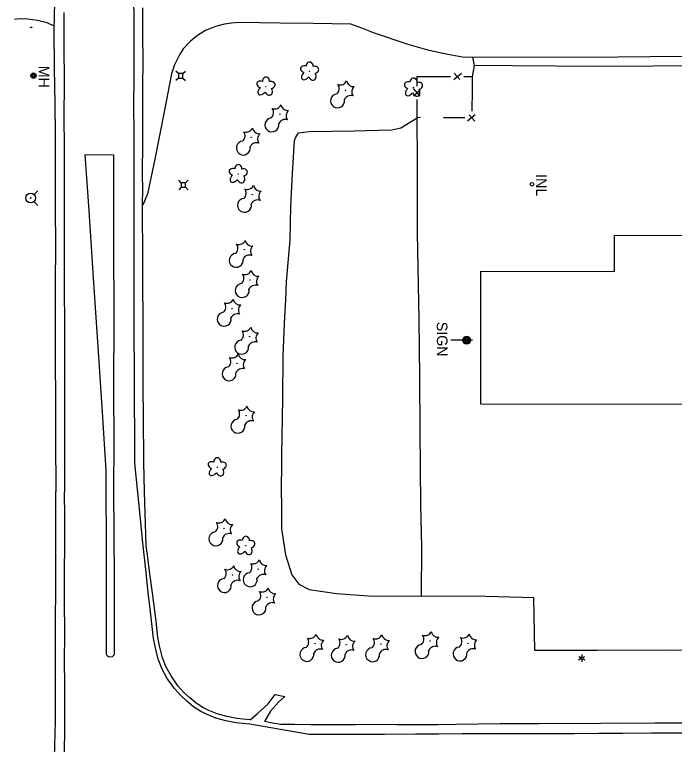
# Model space of a CAD drawing. Extents: x 588843 to 2552415, y 180129 to 269402.
# Drawn here: x 593172.9 to 593545.7, y 183989.9 to 184402 of the extents above; entities that cross this region are included whole.
import ezdxf

# ---------------------------------------------------------------- set-up
doc = ezdxf.new("R2010")
doc.units = 0
for name, color, linetype in [('Default', 7, 'Continuous'), ('E_AREA', 7, 'Continuous'), ('E_BLD', 7, 'Continuous'), ('E_DRN', 7, 'Continuous'), ('E_DRN_Text', 7, 'Continuous'), ('E_DWY', 7, 'Continuous'), ('E_FEN_P', 7, 'Continuous'), ('E_LAND_Vegetation', 7, 'Continuous'), ('E_LTG', 7, 'Continuous'), ('E_MISCPROP', 7, 'Continuous'), ('E_RDWY', 7, 'Continuous'), ('E_RDWY_C_and_G', 7, 'Continuous'), ('E_RDWY_Gravel', 7, 'Continuous'), ('E_SGN', 7, 'Continuous'), ('E_SGN_Text', 7, 'Continuous'), ('E_UTL_AG_Bold', 7, 'Continuous'), ('E_UTL_MH', 7, 'Continuous'), ('E_UTL_MH_Text', 7, 'Continuous'), ('E_UTL_WHydrant', 7, 'Continuous')]:
    doc.layers.add(name, color=color, linetype=linetype)

# ---------------------------------------------------------------- blocks, each defined once
blk = doc.blocks.new('CTRE')
at = {"layer": 'Default'}
blk.add_circle((0, 0), 0.223, dxfattribs=at)
for centre, start, end in [((-11.97, 8.96), 280.2067, 5.97162), ((1.81, 14.92), 220.21132, 305.97623), ((13.83, 5.89), 160.21133, 245.97624), ((-13.83, -5.9), 340.21132, 65.97623), ((-1.81, -14.93), 40.21133, 125.97624), ((12.03, -9.04), 185.92721, 100.25111)]:
    blk.add_arc(centre, 7.87, start, end, dxfattribs=at)
blk = doc.blocks.new('DTRE')
at = {"layer": 'Default'}
blk.add_circle((-0.18, 0), 0.183, dxfattribs=at)
for centre, major_axis, ratio in [((-1.87, 5.32), (1.36, -4.98), 0.782863), ((-5.87, 0.15), (4.93, -0.12), 0.832022), ((4.06, 2.74), (-5.27, -2.93), 0.691916), ((-2.49, -5.24), (1.8, 4.86), 0.716896), ((3.54, -3.71), (-5.01, 4.58), 0.560249)]:
    blk.add_ellipse(centre, major_axis=major_axis, ratio=ratio, start_param=1.570796, end_param=4.712389, dxfattribs=at)
blk = doc.blocks.new('LPOL')
at = {"layer": 'Default'}
for p, q in [((-4, 0), (-1.5, 0)), ((-0.75, 1.3), (-2, 3.46)), ((0.75, 1.3), (2, 3.46)), ((1.5, 0), (4, 0)), ((-2, -3.46), (-0.75, -1.3)), ((2, -3.46), (0.75, -1.3))]:
    blk.add_line(p, q, dxfattribs=at)
for radius in [1.5, 1.5, 1.5, 0.125]:
    blk.add_circle((0, 0), radius, dxfattribs=at)
blk = doc.blocks.new('MHO')
at = {"layer": 'Default'}
for centre, radius in [((0.08, -0.12), 3), ((0.08, -0.12), 2.43), ((0.07, -0.15), 1.94), ((0.02, -0.16), 1.21)]:
    blk.add_circle(centre, radius, dxfattribs=at)
blk = doc.blocks.new('MHT')
at = {"layer": 'E_UTL_MH_Text'}
blk.add_text('MH', height=12, dxfattribs=at).set_placement((-9.81, -6))
blk = doc.blocks.new('CULV2')
at = {"layer": 'E_DRN'}
blk.add_arc((20, 15), 24.6, 216.8699, 323.1301, dxfattribs=at)
blk = doc.blocks.new('HYD')
at = {"layer": 'Default'}
for p, q in [((-3.84, 3.84), (-8.32, 8.32)), ((3.84, 3.84), (8.32, 8.32))]:
    blk.add_line(p, q, dxfattribs=at)
for radius in [5.48, 0.42]:
    blk.add_circle((0, 0), radius, dxfattribs=at)
blk = doc.blocks.new('PED')
at = {"layer": 'Default'}
for p, q in [((-2.5, 2.5), (-5.33, 5.33)), ((2.5, 2.5), (5.33, 5.33)), ((-2.5, -2.5), (-5.33, -5.33)), ((2.5, -2.5), (5.33, -5.33))]:
    blk.add_line(p, q, dxfattribs=at)
blk.add_lwpolyline([(-2.5, -2.5), (2.5, -2.5), (2.5, 2.5), (-2.5, 2.5)], close=True, dxfattribs=at)
blk = doc.blocks.new('POLE')
at = {"layer": 'Default'}
for radius in [4.46, 3.35, 2.23, 1.12]:
    blk.add_circle((0, 0), radius, dxfattribs=at)
blk = doc.blocks.new('SIGN')
at = {"layer": 'Default'}
blk.add_text('SIGN', height=12, dxfattribs=at).set_placement((-18.55, -6))
blk = doc.blocks.new('INLT_18')
at = {"layer": 'E_DRN_Text'}
blk.add_text('INL', height=12, dxfattribs=at).set_placement((-11.03, -6))

msp = doc.modelspace()

# ---------------------------------------------------------------- linework, layer by layer
at = {"layer": 'E_AREA'}
msp.add_lwpolyline([(593431.59, 184377.93), (593432.5, 184373.17)], dxfattribs=at)
at = {"layer": 'E_BLD'}
msp.add_lwpolyline([(593436.4, 184257.03), (593511.82, 184256.91), (593511.85, 184277.37), (593631.64, 184277.17), (593631.66, 184286.82), (593660.64, 184286.78), (593660.63, 184281.05), (593685.36, 184281.01), (593685.2, 184182.16), (593667.98, 184182.19), (593667.94, 184156.61), (593567.5, 184156.78), (593567.54, 184181.81), (593436.27, 184182.03), (593436.4, 184257.03)], close=True, dxfattribs=at)
at = {"layer": 'E_DRN'}
msp.add_circle((593465.21, 184306.21), 1.04, dxfattribs=at)
at = {"layer": 'E_DWY'}
for points in [[(593631.69, 184413.71), (593631.67, 184373.35), (593604.85, 184372.88), (593564.43, 184373), (593502.95, 184372.78), (593454.12, 184373.01), (593432.5, 184373.17), (593431.48, 184366.85)], [(593195.22, 184395.42), (593191.39, 184397.27), (593185.78, 184398.7), (593180.14, 184399.39), (593176.04, 184399.69), (593172.93, 184399.27)], [(593550.18, 184378.37), (593513.66, 184377.95), (593470.82, 184377.84), (593426, 184377.94), (593417.66, 184379.46), (593407.11, 184381.69), (593395.36, 184385.08), (593375.64, 184391.63), (593369.17, 184394.36), (593362.89, 184396.66), (593341.55, 184397.01), (593323.04, 184397.1), (593299.63, 184397.51), (593295.54, 184397.19), (593291.52, 184396.66), (593286.51, 184395.29), (593280.75, 184392.96), (593276.21, 184390.1), (593272.35, 184386.92), (593268.25, 184382.72), (593266.13, 184379.26), (593263.3, 184373.56), (593261.65, 184368.64), (593257.65, 184348.09), (593252.09, 184320.4), (593248.08, 184300.88), (593245.28, 184294.32)], [(593323.63, 184129.02), (593323.87, 184153.18), (593324.38, 184185.29), (593324.62, 184209.34), (593325.48, 184227.67), (593326.23, 184240.93), (593326.6, 184251.11), (593328.55, 184274.9), (593329.02, 184293.67), (593330, 184312.2), (593331.12, 184330.87), (593331.74, 184332.8), (593333.23, 184335.24), (593339.34, 184335.91), (593364.65, 184336.4), (593386.05, 184337.01), (593391.08, 184338.04), (593400.42, 184343.69)], [(593402.45, 184125.26), (593401.98, 184167.17), (593401.81, 184197.24), (593401.41, 184229.76), (593400.56, 184278.64), (593400.59, 184318.89), (593400.42, 184343.72)], [(593323.63, 184129.02), (593323.68, 184111.58), (593325.91, 184096.93), (593329.53, 184085.67), (593333.48, 184080.36), (593339.36, 184077.44), (593354.79, 184075.02), (593372.94, 184073.72), (593402.81, 184073.66)], [(593582.78, 184042.97), (593543.17, 184043.07), (593501.9, 184042.83), (593466.83, 184042.85), (593466.18, 184072.61), (593439.11, 184073.34), (593402.81, 184073.66), (593402.96, 184101.6), (593402.45, 184125.26)]]:
    msp.add_lwpolyline(points, dxfattribs=at)
at = {"layer": 'E_FEN_P'}
for p, q in [((593421.09, 184365.32), (593425.34, 184369)), ((593421.29, 184369.01), (593424.48, 184365.39)), ((593402.07, 184355.96), (593398.35, 184360.18)), ((593398.37, 184356.13), (593401.97, 184359.34)), ((593433.03, 184345.44), (593428.79, 184341.74)), ((593432.84, 184341.74), (593429.65, 184345.36))]:
    msp.add_line(p, q, dxfattribs=at)
for points in [[(593400.33, 184361.61), (593400.31, 184367.06), (593407.04, 184367.05)], [(593407.04, 184367.05), (593419.22, 184367.03)], [(593426.76, 184367.01), (593431.51, 184367), (593431.43, 184359.57)], [(593431.43, 184359.57), (593431.29, 184347.39)], [(593402.24, 184343.85), (593400.42, 184343.72), (593400.37, 184354.07)], [(593427.37, 184343.73), (593415.19, 184343.74)]]:
    msp.add_lwpolyline(points, dxfattribs=at)
at = {"layer": 'E_RDWY'}
for points in [[(593242.46, 184132.19), (593240.85, 184148.67), (593240.82, 184164.6), (593240.73, 184183.98), (593240.65, 184202.42), (593240.54, 184220.47), (593240.49, 184297.36), (593240.52, 184313.89), (593240.45, 184335.12), (593240.29, 184350.9), (593240.44, 184366.42), (593240.41, 184382.33), (593240.4, 184397.38), (593240.34, 184413.18)], [(593200.74, 184403.27), (593200.67, 184385.8), (593200.9, 184362.53), (593200.78, 184344.77), (593200.97, 184326.46), (593200.99, 184307.37), (593200.99, 184282.12), (593201.02, 184252.6), (593201.09, 184221.67), (593201.07, 184185.18), (593201.11, 184151.98), (593201.12, 184132.26)], [(593224.67, 184134.06), (593224.65, 184144.7), (593222.6, 184177.41), (593220.19, 184214.41), (593217.46, 184253.38), (593215.06, 184291.14), (593212.74, 184323.09), (593228.77, 184322.88), (593228.76, 184273.93), (593228.98, 184230.54), (593228.88, 184191.32), (593228.98, 184159.57), (593228.84, 184134.04)], [(593228.84, 184134.04), (593229.19, 184083.4), (593229.22, 184041.59), (593229.11, 184040.53), (593227.97, 184039.4), (593226.76, 184039.23), (593226.02, 184039.44), (593225.21, 184039.94), (593224.93, 184040.58), (593224.79, 184041.58), (593224.81, 184103.77), (593224.67, 184134.06)], [(593197.27, 183805.54), (593197.44, 183822.71), (593197.76, 183835.89), (593198.18, 183850.92), (593198.49, 183867.63), (593198.81, 183882.18), (593199.13, 183891.59), (593199.38, 183906.39), (593199.77, 183920.52), (593200.02, 183936.64), (593200.27, 183958.27), (593200.61, 183972.92), (593201.11, 183986.41), (593201.34, 183997.65), (593201.39, 184009.18), (593201.22, 184023.93), (593201.2, 184036.88), (593201.27, 184052.35), (593201.19, 184071.31), (593201.18, 184086.47), (593201.23, 184103.49), (593201.26, 184118.09), (593201.12, 184132.26)], [(593251.42, 184049.75), (593249.8, 184063.22), (593248.43, 184075.61), (593247.02, 184088.74), (593245.41, 184103.65), (593244.29, 184115.13), (593243.3, 184124.84), (593242.46, 184132.19)], [(593306.1, 184003.8), (593310.18, 184007.26), (593316.1, 184012.72), (593320.22, 184018.08), (593325.5, 184017.03), (593322, 184013.76), (593317.53, 184008.59), (593314.03, 184002.86)], [(593559.88, 183996.27), (593544.92, 183996.23), (593532.75, 183996.23), (593516.32, 183996.12), (593502.75, 183996), (593488.8, 183995.9), (593476.34, 183995.88), (593464.33, 183995.88), (593452.39, 183995.9), (593439.7, 183995.86), (593425.74, 183995.79), (593412.44, 183995.74), (593399.36, 183995.72), (593381.98, 183995.54), (593366.43, 183995.53), (593351.75, 183995.49), (593339.4, 183995.44), (593305.91, 184001.31)]]:
    msp.add_lwpolyline(points, dxfattribs=at)
at = {"layer": 'E_RDWY_C_and_G'}
for points in [[(593305.91, 184001.31), (593301.87, 184001.61), (593297.98, 184002.11), (593292.18, 184003.3), (593286.59, 184004.78), (593281.65, 184006.8), (593278.05, 184008.57), (593273.99, 184011.2), (593270.28, 184014.26), (593266.78, 184017.5), (593263.27, 184021.45), (593259.19, 184027.2), (593256.22, 184032.44), (593254.09, 184038.11), (593252.34, 184045.1), (593251.42, 184049.75)], [(593306.1, 184003.8), (593302.13, 184004.1), (593298.39, 184004.58), (593292.75, 184005.74), (593287.39, 184007.16), (593282.68, 184009.08), (593279.28, 184010.75), (593275.48, 184013.22), (593271.93, 184016.14), (593268.56, 184019.25), (593265.23, 184023.01), (593261.31, 184028.54), (593258.49, 184033.51), (593256.48, 184038.85), (593254.78, 184045.64), (593253.87, 184050.24)]]:
    msp.add_lwpolyline(points, dxfattribs=at)
at = {"layer": 'E_RDWY_Gravel'}
for points in [[(593195.67, 184416.96), (593195.17, 184393.38), (593195.19, 184371.76), (593195.67, 184351.65), (593195.84, 184334.51), (593195.83, 184315.34), (593195.77, 184293.18), (593195.96, 184271.16), (593195.88, 184250.04), (593195.85, 184228.6), (593195.91, 184206.82), (593196, 184184), (593196.06, 184162.17), (593196.15, 184132.7)], [(593246.35, 184132.48), (593245.99, 184149.18), (593245.82, 184175.7), (593245.63, 184190.91), (593245.53, 184205.49), (593245.5, 184220.98), (593245.27, 184297.56), (593245.38, 184300.64), (593245.27, 184314.1), (593245.4, 184327.5), (593245.46, 184346.59), (593245.4, 184362.19), (593245.49, 184375.02), (593245.41, 184390.88), (593245.34, 184405.88)], [(593195.42, 183982.48), (593195.95, 184002.85), (593195.97, 184014.46), (593196.03, 184027.87), (593196.08, 184040.2), (593196.05, 184051.67), (593196.07, 184062.97), (593196.28, 184074.49), (593196.25, 184091.41), (593196.19, 184108.64), (593196.28, 184121.87), (593196.15, 184132.7)], [(593253.87, 184050.24), (593252.91, 184059.48), (593250.89, 184075.43), (593249.33, 184086.19), (593247.96, 184096.97), (593247.31, 184101.9), (593247.03, 184108.35), (593246.35, 184132.48)], [(593553.63, 184001.81), (593544.45, 184001.8), (593534.65, 184001.9), (593523.49, 184001.79), (593513.53, 184001.83), (593503.96, 184001.67), (593494.19, 184001.6), (593483.92, 184001.62), (593469.07, 184001.48), (593457.59, 184001.43), (593447.25, 184001.47), (593434.77, 184001.37), (593422.26, 184001.09), (593412.28, 184001.03), (593402.4, 184000.97), (593388.91, 184000.9), (593377.36, 184001.05), (593365.47, 184000.89), (593354.69, 184000.89), (593340.27, 184001), (593331.02, 184001.09), (593323.38, 184001.13), (593318.54, 184001.89), (593314.03, 184002.86)]]:
    msp.add_lwpolyline(points, dxfattribs=at)
at = {"layer": 'E_SGN'}
msp.add_lwpolyline([(593419.45, 184218.27), (593431.64, 184218.31)], dxfattribs=at)

# ---------------------------------------------------------------- block references
at = {"layer": 'E_DRN', "xscale": 0.027575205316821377, "yscale": 0.027575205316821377, "rotation": 176.3411170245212}
msp.add_blockref('CULV2', (593182.82, 184394.49), dxfattribs=at)
at = {"layer": 'E_DRN_Text', "xscale": 0.49999999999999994, "yscale": 0.5, "rotation": -90.03098035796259}
msp.add_blockref('INLT_18', (593470.5, 184306.37), dxfattribs=at)
at = {"layer": 'E_LAND_Vegetation', "yscale": 0.5}
for name, p, xscale, rotation in [('DTRE', (593339.55, 184369.82), 0.49999999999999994, -90.03098035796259), ('DTRE', (593314.89, 184361.28), 0.49999999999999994, -90.03098035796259), ('CTRE', (593359.86, 184359.29), 0.49999999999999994, -90.03098035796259), ('DTRE', (593398.24, 184360.78), 0.49999999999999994, -90.03098035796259), ('CTRE', (593322.79, 184345.76), 0.49999999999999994, -90.03098035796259), ('CTRE', (593306.67, 184332.65), 0.49999999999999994, -90.03098035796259), ('DTRE', (593299.25, 184311.88), 0.49999999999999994, -90.03098035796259), ('CTRE', (593307.3, 184300.3), 0.49999999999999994, -90.03098035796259), ('CTRE', (593302.65, 184269.23), 0.49999999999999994, -90.03098035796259), ('CTRE', (593305.99, 184252.19), 0.49999999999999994, -90.03098035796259), ('CTRE', (593295.8, 184235.99), 0.49999999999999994, -90.03098035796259), ('CTRE', (593305.72, 184220.18), 0.49999999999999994, -90.03098035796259), ('CTRE', (593298.61, 184205.12), 0.49999999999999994, -90.03098035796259), ('CTRE', (593303.61, 184175.59), 0.49999999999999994, -90.03098035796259), ('DTRE', (593287.37, 184146.34), 0.49999999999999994, -90.03098035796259), ('CTRE', (593291.24, 184111.98), 0.5, -90.44645755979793), ('DTRE', (593303.51, 184102), 0.5, -90.44645755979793), ('CTRE', (593310.55, 184088.85), 0.5, -90.44645755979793), ('CTRE', (593296.03, 184085.56), 0.5, -90.44645755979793), ('CTRE', (593315.57, 184072.97), 0.5, -90.44645755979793), ('CTRE', (593342.6, 184046.71), 0.5, -90.44645755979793), ('CTRE', (593360.3, 184046.21), 0.5, -90.44645755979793), ('CTRE', (593379.74, 184046.51), 0.5, -90.44645755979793), ('CTRE', (593407.66, 184048.33), 0.5, -90.44645755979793), ('CTRE', (593429.13, 184046.95), 0.5, -90.44645755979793)]:
    msp.add_blockref(name, p, dxfattribs=dict(at, xscale=xscale, rotation=rotation))
at = {"layer": 'E_LTG', "xscale": 0.5, "yscale": 0.5, "rotation": -90.44645755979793}
msp.add_blockref('LPOL', (593493.31, 184038.61), dxfattribs=at)
at = {"layer": 'E_MISCPROP', "xscale": 0.49999999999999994, "yscale": 0.5000000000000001, "rotation": -89.630833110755}
msp.add_blockref('POLE', (593428.3, 184218.11), dxfattribs=at)
at = {"layer": 'E_SGN_Text', "xscale": 0.49999999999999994, "yscale": 0.5000000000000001, "rotation": -89.630833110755}
msp.add_blockref('SIGN', (593414.49, 184219.27), dxfattribs=at)
at = {"layer": 'E_UTL_AG_Bold', "xscale": 0.49999999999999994, "yscale": 0.49999999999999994, "rotation": -90.119079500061}
for p in [(593266.76, 184367.44), (593268.31, 184305.78)]:
    msp.add_blockref('PED', p, dxfattribs=at)
at = {"layer": 'E_UTL_MH', "xscale": 0.49999999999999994, "yscale": 0.49999999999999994, "rotation": -90.119079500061}
msp.add_blockref('MHO', (593183.69, 184367.58), dxfattribs=at)
at = {"layer": 'E_UTL_MH_Text', "xscale": 0.49999999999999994, "yscale": 0.49999999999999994, "rotation": -90.119079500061}
msp.add_blockref('MHT', (593189.52, 184368.22), dxfattribs=at)
at = {"layer": 'E_UTL_WHydrant', "xscale": 0.49999999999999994, "yscale": 0.49999999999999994, "rotation": -90.119079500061}
msp.add_blockref('HYD', (593181.97, 184298.42), dxfattribs=at)

doc.saveas('drawing.dxf')
